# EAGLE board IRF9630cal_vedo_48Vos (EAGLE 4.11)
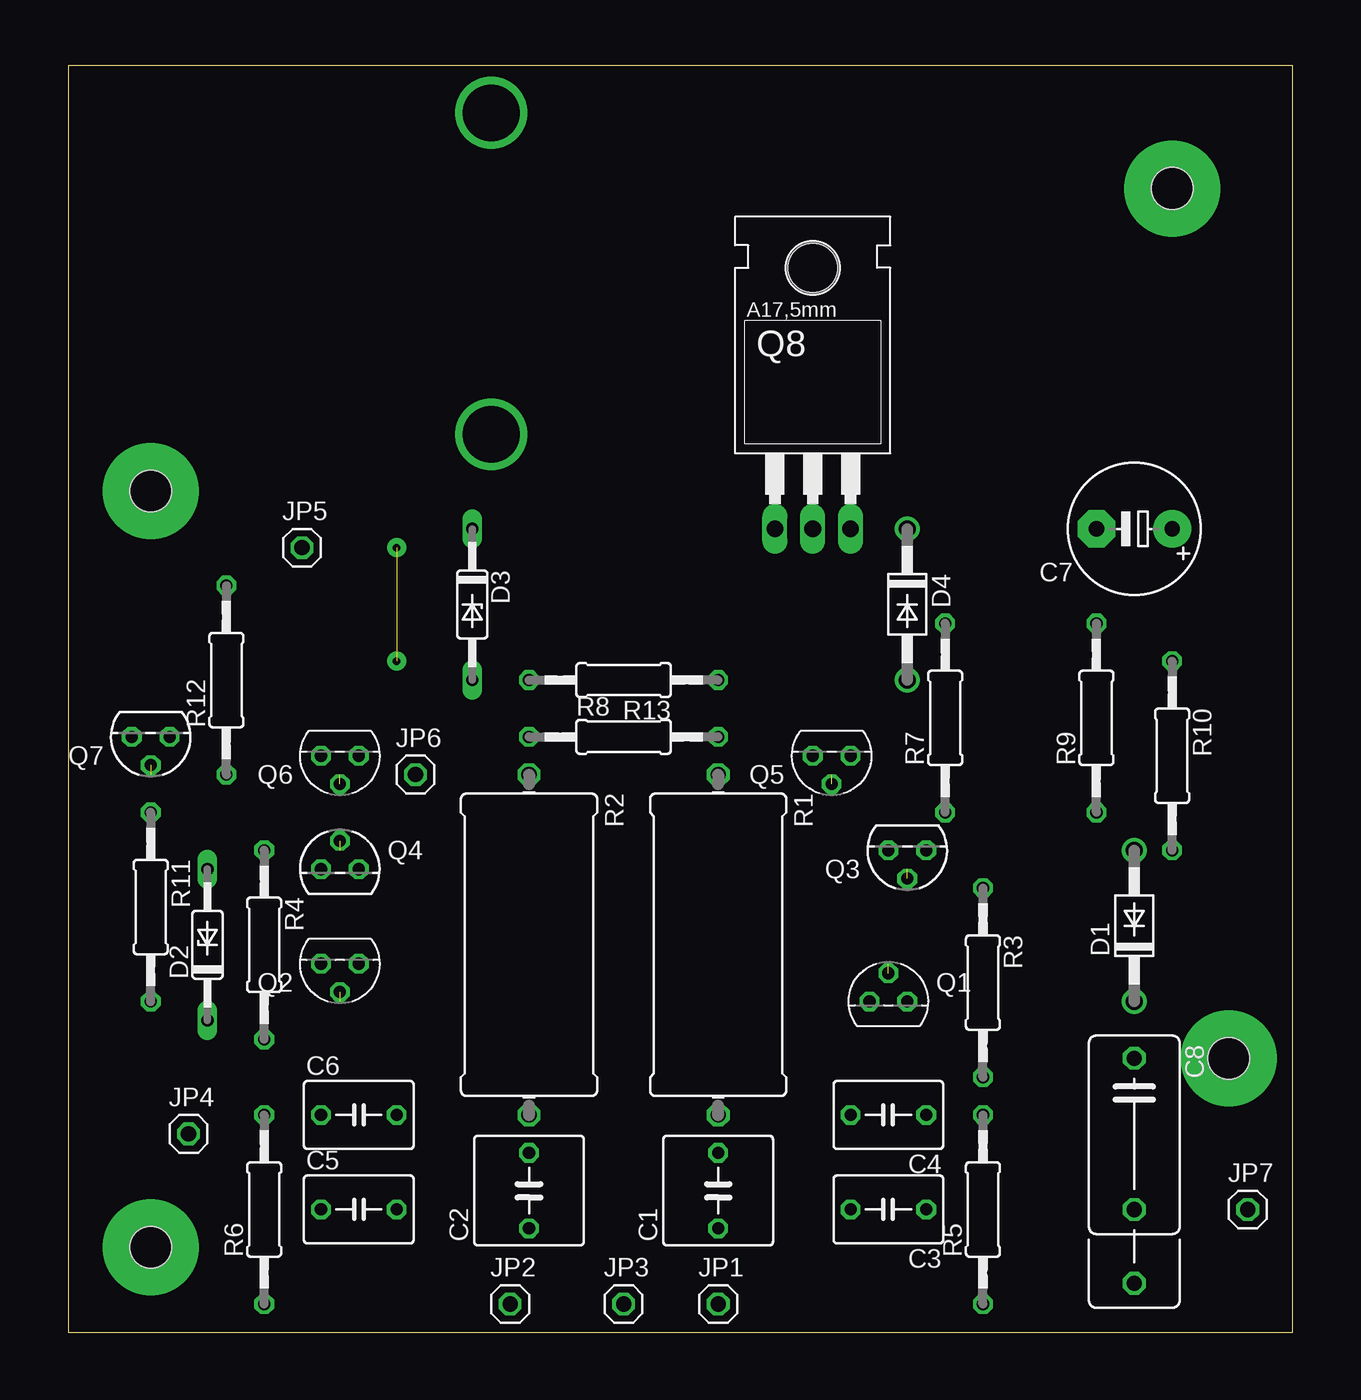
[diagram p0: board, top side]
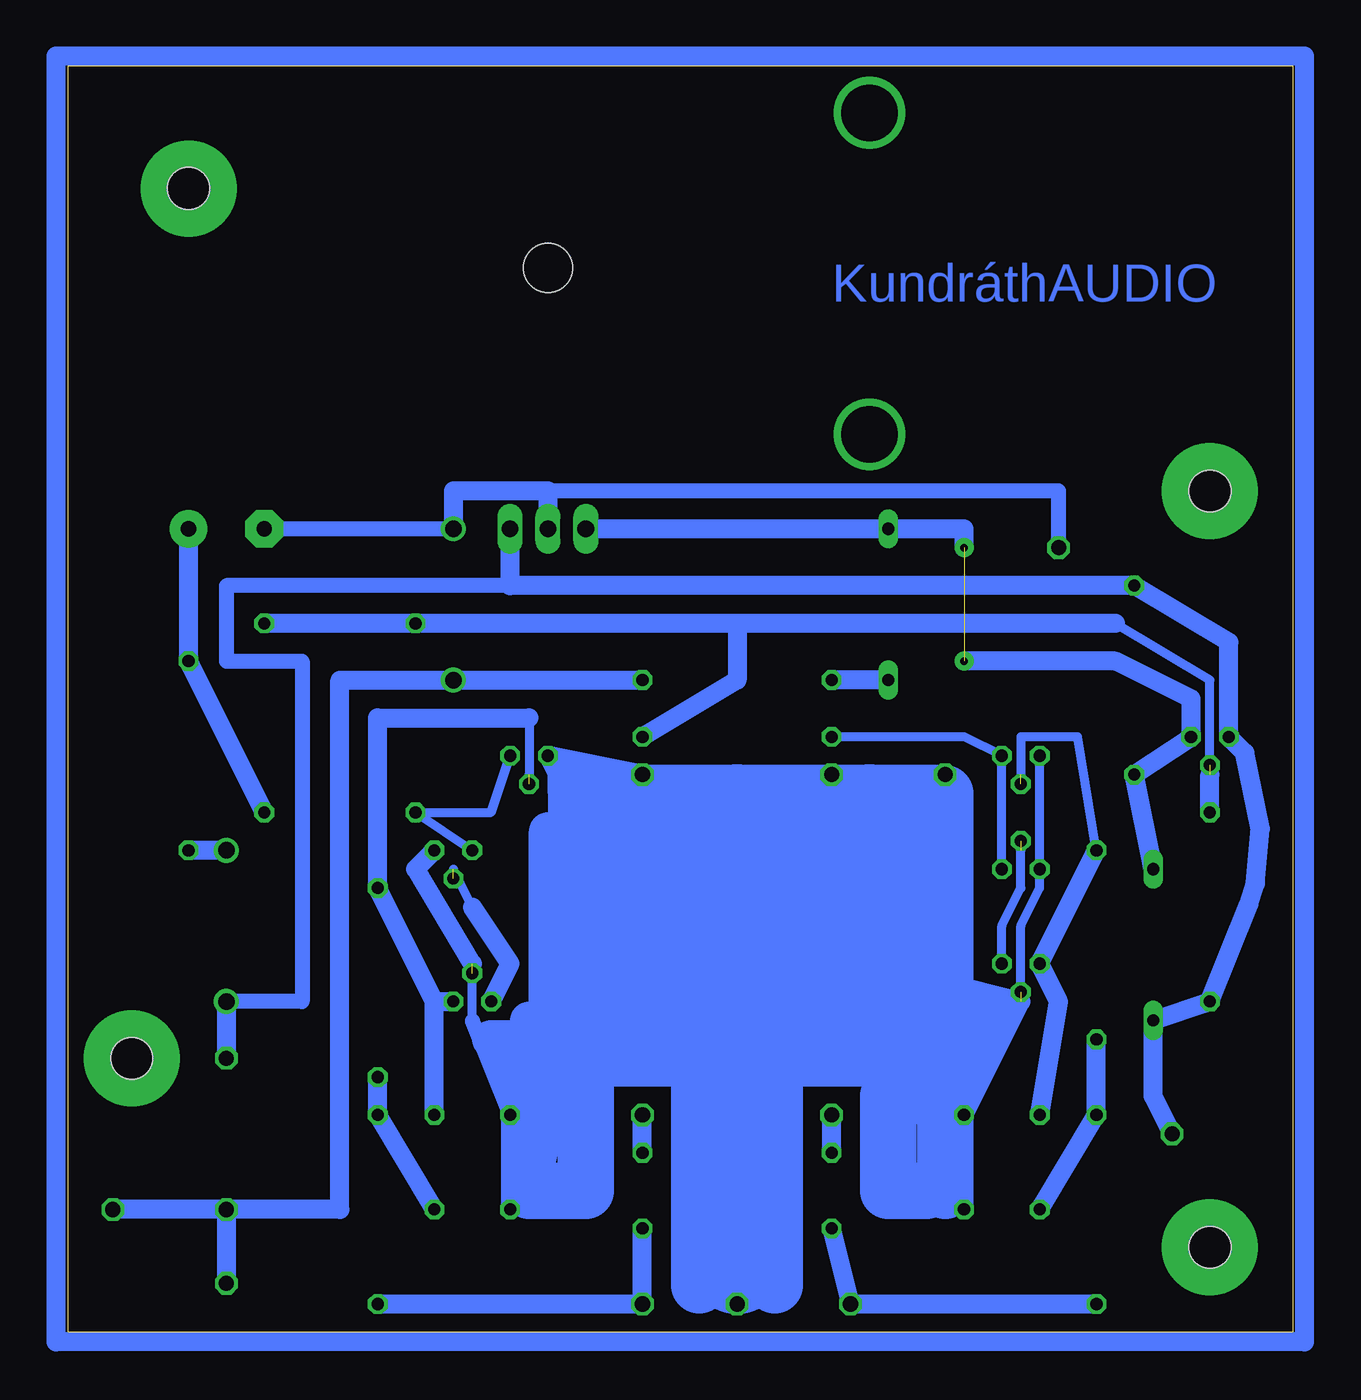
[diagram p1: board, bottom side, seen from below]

Size 82.22 x 85.08 mm. Coordinates in mm from the lower left corner, seen from the top.
Outline: 0,0 82.22,0 82.22,85.08 0,85.08 0,0
Copper layers (1*16): Top 0.035mm / dielectric 1.5mm / Bottom 0.035mm
Design rules "default": minimum track width 10mil, minimum drill 24mil, track to track 8mil, track to pad 8mil, pad to pad 8mil, via to via 8mil, smd to smd 8mil, copper to edge 40mil, drill to drill 8mil, minimum pad ring 10mil, minimum via ring 8mil, stop-mask expansion 4mil, vias tented up to drill 0mil, thermal gap 10mil
Holes 2.8 mm at 5.55,56.51 74.13,76.83 77.94,18.41 5.55,5.71

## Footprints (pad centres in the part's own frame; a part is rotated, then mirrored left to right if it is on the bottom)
C050-075X075 = drill 0.813 octagon: 1 -2.54,0; 2 2.54,0
C050-045X075 = drill 0.813 octagon: 1 -2.54,0; 2 2.54,0
E5-8,5 = drill 1.016 pad 2.54 round: + -2.54,0 | drill 1.016 pad 2.54 octagon: - 2.54,0
C102_152-062X184 = drill 1.016 octagon: 1 -5.08,0; 2 5.08,0; 3 10.033,0
DO41-10 = drill 1.118 round: A 5.08,0; C -5.08,0
DO35Z10 = drill 0.813 long: A 5.08,0; C -5.08,0
1X01 = drill 1.016 octagon: 1 0,0
TO92 = drill 0.813 octagon: 1 1.27,0; 2 0,1.905; 3 -1.27,0
TO220 = drill 1.118 long: 1 -2.54,-6.35; 2 0,-6.35; 3 2.54,-6.35 | hole 3.302: 0,11.176
0922/22 = drill 1.016 octagon: 1 -11.43,0; 2 11.43,0
0207/12 = drill 0.813 octagon: 1 -6.35,0; 2 6.35,0

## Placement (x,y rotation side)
C1  100nF  [C050-075X075]  43.65,9.52 90 top
C2  100nF  [C050-075X075]  30.95,9.52 90 top
C3  2,2uF  [C050-045X075]  55.08,8.25 180 top
C4  2,2uF  [C050-045X075]  55.08,14.6 180 top
C5  2,2uF  [C050-045X075]  19.52,8.25 0 top
C6  2,2uF  [C050-045X075]  19.52,14.6 0 top
C7  33uF/200V  [E5-8,5]  71.59,53.97 180 top
C8  220nF/200V  [C102_152-062X184]  71.59,13.33 270 top
D1  1N4007  [DO41-10]  71.59,27.3 90 top
D2  ZPD12  [DO35Z10]  9.36,26.03 90 top
D3  ZPD75  [DO35Z10]  27.14,48.89 270 top
D4  1N4007  [DO41-10]  56.35,48.89 270 top
JP1  Left  [1X01]  43.65,1.9 0 top
JP2  Right  [1X01]  29.68,1.9 0 top
JP3  GND  [1X01]  37.3,1.9 0 top
JP4  +50V  [1X01]  8.09,13.33 0 top
JP5  +Relé  [1X01]  15.71,52.7 0 top
JP6  -Relé  [1X01]  23.33,37.46 0 top
JP7  -50V  [1X01]  79.21,8.25 0 top
Q1  BC182  [TO92]  55.08,22.22 0 top
Q2  BC182  [TO92]  18.25,24.76 180 top
Q3  BC212  [TO92]  56.35,32.38 180 top
Q4  BC212  [TO92]  18.25,31.11 0 top
Q5  BC182  [TO92]  51.27,38.73 180 top
Q6  BC182  [TO92]  18.25,38.73 180 top
Q7  BC212  [TO92]  5.55,40 180 top
Q8  IRF9630  [TO220]  50,60.32 0 top
R1  10/5W  [0922/22]  43.65,26.03 270 top
R2  10/5W  [0922/22]  30.95,26.03 270 top
R3  22K  [0207/12]  61.43,23.49 270 top
R4  22K  [0207/12]  13.17,26.03 270 top
R5  22K  [0207/12]  61.43,8.25 90 top
R6  22K  [0207/12]  13.17,8.25 90 top
R7  47K  [0207/12]  58.89,41.27 90 top
R8  47K  [0207/12]  37.3,40 0 top
R9  47K  [0207/12]  69.05,41.27 90 top
R10  1K  [0207/12]  74.13,38.73 270 top
R11  5,6K  [0207/12]  5.55,28.57 270 top
R12  22K  [0207/12]  10.63,43.81 90 top
R13  22K  [0207/12]  37.3,43.81 180 top

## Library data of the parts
C1-C8 R1-R13 = rcl
D1-D4 = diode
JP1-JP7 = pinhead
Q1 Q2 Q5 Q6 = transistor-npn
Q3 Q4 Q7 = transistor-pnp
Q8 = transistor-fet

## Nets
N$1: C1.2 R1.2
N$2: C1.1 JP1.1 R5.1
N$3: C3.1 R3.2 R5.2
N$5: Q1.3 Q3.2
N$6: D2.A D3.C Q7.3 Q8.1 R12.1
N$7: Q3.1 Q5.3 R7.1
N$8: Q4.1 Q6.3 R8.1
N$9: Q2.3 Q4.2
N$10: C5.1 R4.2 R6.2
N$12: C4.1 Q1.1 Q5.2 R3.1
N$13: C2.2 R2.2
N$14: C2.1 JP2.1 R6.1
N$15: Q7.2 R7.2 R8.2 R9.2 R11.1
N$16: C8.1 D1.C D2.C JP4.1 Q7.1 Q8.3 R11.2 R12.2
N$17: D1.A R10.2
N$18: C7.+ R9.1 R10.1
N$19: C3.2 C4.2 C5.2 C6.2 JP3.1 JP6.1 Q1.2 Q2.2 Q3.3 Q4.3 Q5.1 Q6.1 R1.1 R2.1
N$20: D3.A R13.2
N$21: C8.2 D4.A JP7.1 R13.1
N$23: C6.1 Q2.1 Q6.2 R4.1
N$35: C7.- D4.C JP5.1 Q8.2

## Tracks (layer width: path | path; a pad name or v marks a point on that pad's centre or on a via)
N$1
  Bottom 1.27: C1.2 R1.2
N$2
  Bottom 1.27: C1.1 JP1.1 R5.1
N$3
  Bottom 1.27: C3.1 R5.2 R3.2
N$4
  Bottom 2.54: 39.84,18.41 48.73,18.41 | 48.73,18.41 51.27,18.41 52.54,18.41 52.54,17.14 | 48.73,18.41 48.73,33.65
  Bottom 3.81: 39.84,18.41 51.27,18.41
N$5  (1 unrouted)
  Bottom 0.61: 55.08,28.57 56.35,31.11
  Bottom 1.27: Q1.3 52.54,24.76 55.08,28.57
N$6  (via drill 0.5 pad 1.27)  (1 unrouted)
  Bottom 1.27: v22.06,45.08 11.9,45.08 6.82,42.54 Q7.3 R12.1 D2.A | Q8.1 D3.C 22.06,53.97 v22.06,52.7
N$7
  Bottom 0.61: Q3.1 R7.1 53.81,34.92 Q5.3
N$8
  Bottom 0.61: Q4.1 Q6.3 22.06,40 R8.1
N$9  (1 unrouted)
  Bottom 0.61: 18.25,32.38 18.25,29.84 19.52,27.3 Q2.3
N$10
  Bottom 1.27: R4.2 R6.2 C5.1
N$11
  Bottom 6.452: 30.95,34.92 46.19,34.92 46.19,20.95 41.11,20.95 41.11,29.84
N$12  (1 unrouted)
  Bottom 0.61: 51.27,41.27 51.27,37.46
  Bottom 1.27: 57.62,22.22 Q1.1 | C4.1 57.62,22.22 | 57.62,22.22 R3.1 61.43,41.27 51.27,41.27
N$13
  Bottom 1.27: C2.2 R2.2
N$14
  Bottom 1.27: R6.1 JP2.1 C2.1
N$15  (1 unrouted)
  Bottom 0.61: 5.55,37.46 5.55,43.81 11.9,47.62
  Bottom 1.27: R9.2 R7.2 37.3,47.62 | R11.1 5.55,37.46 | 37.3,47.62 37.3,43.81 R8.2 | 11.9,47.62 37.3,47.62
N$16
  Bottom 1.016: D1.C 66.51,22.22 66.51,45.08 71.59,45.08 71.59,50.16 52.54,50.16
  Bottom 1.27: D1.C C8.1 | Q8.3 52.54,50.16 R12.2 4.28,46.35 Q7.1 3.21,38.93 2.17,33.84 2.5,30.14 2.94,28.75 R11.2 D2.C 9.36,15.87 JP4.1
N$17
  Bottom 1.27: D1.A R10.2
N$18
  Bottom 1.27: R9.1 R10.1 C7.+
N$19  (2 unrouted)
  Bottom 0.61: 55.08,20.95 55.08,24.76 | 18.25,22.22 18.25,27.3 16.98,29.84 Q4.3 Q6.1
  Bottom 1.016: C4.2 55.08,20.95
  Bottom 1.27: C3.2 C4.2 48.73,19.68 48.73,33.65 | C5.2 C6.2 18.25,22.22 23.33,23.49 | 37.3,37.46 R2.1 JP6.1 23.33,36.19 | 37.3,37.46 R1.1 Q5.1 48.73,36.19 | 37.3,4.44 JP3.1 | 37.3,37.46 37.3,34.92 | 55.08,24.76 58.89,31.11 Q3.3
  Bottom 2.54: 48.73,37.46 48.73,36.19 48.73,33.65 | 51.27,19.68 52.54,19.68 | 48.73,19.68 51.27,19.68 | 51.27,19.68 51.27,20.95 | 51.27,19.68 53.81,19.68
  Bottom 3.81: 23.33,23.49 23.33,36.19
  Bottom 6.452: 37.3,34.92 37.3,4.44
N$20
  Bottom 1.27: D3.A R13.2
N$21
  Bottom 1.27: R13.1 D4.A 63.97,43.81 63.97,8.25 C8.2 | C8.2 71.59,3.17 | C8.2 JP7.1
N$23  (1 unrouted)
  Bottom 0.61: 18.25,37.46 18.25,40 14.44,40 R4.1
  Bottom 1.27: C6.1 15.71,22.22 Q2.1 R4.1
N$24
  Bottom 6.452: 30.95,32.38 30.95,20.95 34.76,20.95
N$25
  Bottom 6.452: 28.41,20.95 28.41,34.92
N$26
  Bottom 2.54: 50,20.95 50,33.65
N$27
  Bottom 3.81: 28.41,36.19 24.6,36.19 24.6,19.68 34.76,19.68
N$28
  Bottom 3.81: 20.79,20.95 23.33,20.95
N$29
  Bottom 3.81: 22.06,19.68 24.6,19.68
N$30
  Bottom 3.81: 22.06,18.41 34.76,18.41
N$31
  Bottom 3.81: 34.76,3.17 34.76,17.14
N$32
  Bottom 3.81: 39.84,3.17 39.84,17.14
N$33
  Bottom 3.81: 23.33,9.52 23.33,15.87 27.14,15.87 27.14,9.52 24.6,9.52
N$34
  Bottom 3.81: 51.27,9.52 47.46,9.52 47.46,17.14 51.27,17.14 51.27,12.06
N$35
  Bottom 1.016: D4.C C7.- | 50,56.51 15.71,56.51 JP5.1
  Bottom 1.27: Q8.2 50,56.51 56.35,56.51 D4.C
N$36
  Bottom 1.27: -0.8,85.72 83.02,85.72 83.02,-0.64 -0.8,-0.64 -0.8,85.72
N$38  (via drill 0.5 pad 6.45)
  other vias: 5.55,56.51
N$39  (via drill 0.5 pad 6.45)
  other vias: 74.13,76.83
N$40  (via drill 0.5 pad 6.45)
  other vias: 5.55,5.71
N$41  (via drill 0.5 pad 6.45)
  other vias: 77.94,18.41
S$1  (via drill 3.81)
  other vias: 28.41,60.32
S$2  (via drill 3.81)
  other vias: 28.41,81.91

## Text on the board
Bottom: KundráthAUDIO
